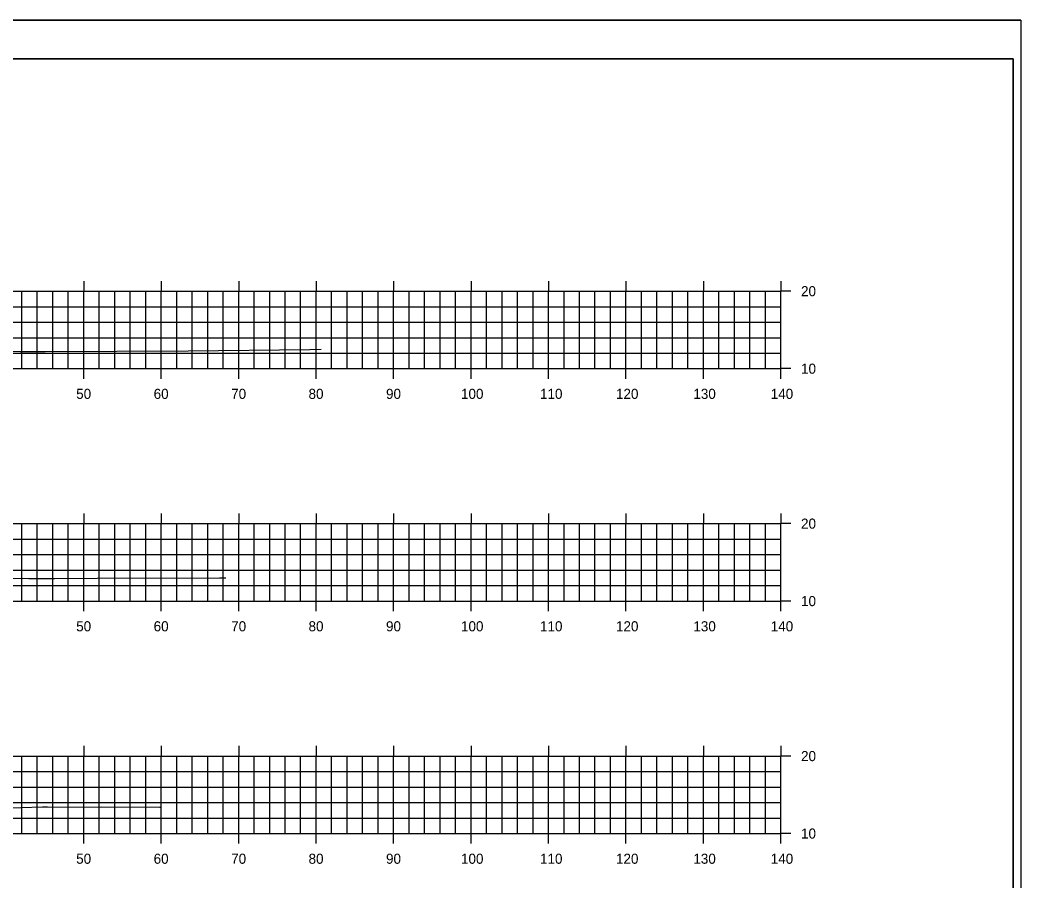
# Model space of a CAD drawing. Extents: x 40011 to 50684, y 49949 to 72236.
# Drawn here: x 42283.1 to 42412.4, y 69083.5 to 69194.6 of the extents above; entities that cross this region are included whole.
import ezdxf

# ---------------------------------------------------------------- set-up
doc = ezdxf.new("R2010")
doc.units = 0
for name, color, linetype in [('1', 7, 'Continuous'), ('41', 7, 'Continuous'), ('51', 7, 'Continuous'), ('53', 7, 'Continuous'), ('55', 7, 'Continuous'), ('57', 7, 'Continuous'), ('60', 7, 'Continuous')]:
    doc.layers.add(name, color=color, linetype=linetype)

msp = doc.modelspace()

# ---------------------------------------------------------------- linework, layer by layer
at = {"layer": '1'}
for p, q in [((42412.37, 69194.6), (42062.98, 69194.6)), ((42411.37, 69189.6), (42081.37, 69189.6)), ((42411.37, 68979.6), (42411.37, 69189.6))]:
    msp.add_line(p, q, dxfattribs=at)
at = {"layer": '41'}
for points in [[(42062.98, 69194.6), (42412.37, 69194.6), (42412.37, 68974.6), (42062.98, 68974.6)], [(42081.37, 69189.6), (42411.37, 69189.6), (42411.37, 68979.6), (42081.37, 68979.6)]]:
    msp.add_lwpolyline(points, close=True, dxfattribs=at)
at = {"layer": '51'}
for p, q in [((42283.37, 69149.6), (42283.37, 69159.6)), ((42285.37, 69149.6), (42285.37, 69159.6)), ((42287.37, 69149.6), (42287.37, 69159.6)), ((42289.37, 69149.6), (42289.37, 69159.6)), ((42293.37, 69149.6), (42293.37, 69159.6)), ((42295.37, 69149.6), (42295.37, 69159.6)), ((42297.37, 69149.6), (42297.37, 69159.6)), ((42299.37, 69149.6), (42299.37, 69159.6)), ((42303.37, 69149.6), (42303.37, 69159.6)), ((42305.37, 69149.6), (42305.37, 69159.6)), ((42307.37, 69149.6), (42307.37, 69159.6)), ((42309.37, 69149.6), (42309.37, 69159.6)), ((42313.37, 69149.6), (42313.37, 69159.6)), ((42315.37, 69149.6), (42315.37, 69159.6)), ((42317.37, 69149.6), (42317.37, 69159.6)), ((42319.37, 69149.6), (42319.37, 69159.6)), ((42323.37, 69149.6), (42323.37, 69159.6)), ((42325.37, 69149.6), (42325.37, 69159.6)), ((42327.37, 69149.6), (42327.37, 69159.6)), ((42329.37, 69149.6), (42329.37, 69159.6)), ((42333.37, 69149.6), (42333.37, 69159.6)), ((42335.37, 69149.6), (42335.37, 69159.6)), ((42337.37, 69149.6), (42337.37, 69159.6)), ((42339.37, 69149.6), (42339.37, 69159.6)), ((42343.37, 69149.6), (42343.37, 69159.6)), ((42345.37, 69149.6), (42345.37, 69159.6)), ((42347.37, 69149.6), (42347.37, 69159.6)), ((42349.37, 69149.6), (42349.37, 69159.6)), ((42353.37, 69149.6), (42353.37, 69159.6)), ((42355.37, 69149.6), (42355.37, 69159.6)), ((42357.37, 69149.6), (42357.37, 69159.6)), ((42359.37, 69149.6), (42359.37, 69159.6)), ((42363.37, 69149.6), (42363.37, 69159.6)), ((42365.37, 69149.6), (42365.37, 69159.6)), ((42367.37, 69149.6), (42367.37, 69159.6)), ((42369.37, 69149.6), (42369.37, 69159.6)), ((42373.37, 69149.6), (42373.37, 69159.6)), ((42375.37, 69149.6), (42375.37, 69159.6)), ((42377.37, 69149.6), (42377.37, 69159.6)), ((42379.37, 69149.6), (42379.37, 69159.6)), ((42381.37, 69149.6), (42381.37, 69159.6)), ((42382.67, 69159.6), (42381.37, 69159.6)), ((42101.37, 69149.6), (42381.37, 69149.6)), ((42291.37, 69148.3), (42291.37, 69149.6)), ((42301.37, 69148.3), (42301.37, 69149.6)), ((42311.37, 69148.3), (42311.37, 69149.6)), ((42321.37, 69148.3), (42321.37, 69149.6)), ((42331.37, 69148.3), (42331.37, 69149.6)), ((42341.37, 69148.3), (42341.37, 69149.6)), ((42351.37, 69148.3), (42351.37, 69149.6)), ((42361.37, 69148.3), (42361.37, 69149.6)), ((42371.37, 69148.3), (42371.37, 69149.6)), ((42381.37, 69148.3), (42381.37, 69149.6)), ((42382.67, 69149.6), (42381.37, 69149.6)), ((42283.37, 69119.6), (42283.37, 69129.6)), ((42285.37, 69119.6), (42285.37, 69129.6)), ((42287.37, 69119.6), (42287.37, 69129.6)), ((42289.37, 69119.6), (42289.37, 69129.6)), ((42293.37, 69119.6), (42293.37, 69129.6)), ((42295.37, 69119.6), (42295.37, 69129.6)), ((42297.37, 69119.6), (42297.37, 69129.6)), ((42299.37, 69119.6), (42299.37, 69129.6)), ((42303.37, 69119.6), (42303.37, 69129.6)), ((42305.37, 69119.6), (42305.37, 69129.6)), ((42307.37, 69119.6), (42307.37, 69129.6)), ((42309.37, 69119.6), (42309.37, 69129.6)), ((42313.37, 69119.6), (42313.37, 69129.6)), ((42315.37, 69119.6), (42315.37, 69129.6)), ((42317.37, 69119.6), (42317.37, 69129.6)), ((42319.37, 69119.6), (42319.37, 69129.6)), ((42323.37, 69119.6), (42323.37, 69129.6)), ((42325.37, 69119.6), (42325.37, 69129.6)), ((42327.37, 69119.6), (42327.37, 69129.6)), ((42329.37, 69119.6), (42329.37, 69129.6)), ((42333.37, 69119.6), (42333.37, 69129.6)), ((42335.37, 69119.6), (42335.37, 69129.6)), ((42337.37, 69119.6), (42337.37, 69129.6)), ((42339.37, 69119.6), (42339.37, 69129.6)), ((42343.37, 69119.6), (42343.37, 69129.6)), ((42345.37, 69119.6), (42345.37, 69129.6)), ((42347.37, 69119.6), (42347.37, 69129.6)), ((42349.37, 69119.6), (42349.37, 69129.6)), ((42353.37, 69119.6), (42353.37, 69129.6)), ((42355.37, 69119.6), (42355.37, 69129.6)), ((42357.37, 69119.6), (42357.37, 69129.6)), ((42359.37, 69119.6), (42359.37, 69129.6)), ((42363.37, 69119.6), (42363.37, 69129.6)), ((42365.37, 69119.6), (42365.37, 69129.6)), ((42367.37, 69119.6), (42367.37, 69129.6)), ((42369.37, 69119.6), (42369.37, 69129.6)), ((42373.37, 69119.6), (42373.37, 69129.6)), ((42375.37, 69119.6), (42375.37, 69129.6)), ((42377.37, 69119.6), (42377.37, 69129.6)), ((42379.37, 69119.6), (42379.37, 69129.6)), ((42381.37, 69119.6), (42381.37, 69129.6)), ((42382.67, 69129.6), (42381.37, 69129.6)), ((42101.37, 69119.6), (42381.37, 69119.6)), ((42291.37, 69118.3), (42291.37, 69119.6)), ((42301.37, 69118.3), (42301.37, 69119.6)), ((42311.37, 69118.3), (42311.37, 69119.6)), ((42321.37, 69118.3), (42321.37, 69119.6)), ((42331.37, 69118.3), (42331.37, 69119.6)), ((42341.37, 69118.3), (42341.37, 69119.6)), ((42351.37, 69118.3), (42351.37, 69119.6)), ((42361.37, 69118.3), (42361.37, 69119.6)), ((42371.37, 69118.3), (42371.37, 69119.6)), ((42381.37, 69118.3), (42381.37, 69119.6)), ((42382.67, 69119.6), (42381.37, 69119.6)), ((42283.37, 69089.6), (42283.37, 69099.6)), ((42285.37, 69089.6), (42285.37, 69099.6)), ((42287.37, 69089.6), (42287.37, 69099.6)), ((42289.37, 69089.6), (42289.37, 69099.6)), ((42293.37, 69089.6), (42293.37, 69099.6)), ((42295.37, 69089.6), (42295.37, 69099.6)), ((42297.37, 69089.6), (42297.37, 69099.6)), ((42299.37, 69089.6), (42299.37, 69099.6)), ((42303.37, 69089.6), (42303.37, 69099.6)), ((42305.37, 69089.6), (42305.37, 69099.6)), ((42307.37, 69089.6), (42307.37, 69099.6)), ((42309.37, 69089.6), (42309.37, 69099.6)), ((42313.37, 69089.6), (42313.37, 69099.6)), ((42315.37, 69089.6), (42315.37, 69099.6)), ((42317.37, 69089.6), (42317.37, 69099.6)), ((42319.37, 69089.6), (42319.37, 69099.6)), ((42323.37, 69089.6), (42323.37, 69099.6)), ((42325.37, 69089.6), (42325.37, 69099.6)), ((42327.37, 69089.6), (42327.37, 69099.6)), ((42329.37, 69089.6), (42329.37, 69099.6)), ((42333.37, 69089.6), (42333.37, 69099.6)), ((42335.37, 69089.6), (42335.37, 69099.6)), ((42337.37, 69089.6), (42337.37, 69099.6)), ((42339.37, 69089.6), (42339.37, 69099.6)), ((42343.37, 69089.6), (42343.37, 69099.6)), ((42345.37, 69089.6), (42345.37, 69099.6)), ((42347.37, 69089.6), (42347.37, 69099.6)), ((42349.37, 69089.6), (42349.37, 69099.6)), ((42353.37, 69089.6), (42353.37, 69099.6)), ((42355.37, 69089.6), (42355.37, 69099.6)), ((42357.37, 69089.6), (42357.37, 69099.6)), ((42359.37, 69089.6), (42359.37, 69099.6)), ((42363.37, 69089.6), (42363.37, 69099.6)), ((42365.37, 69089.6), (42365.37, 69099.6)), ((42367.37, 69089.6), (42367.37, 69099.6)), ((42369.37, 69089.6), (42369.37, 69099.6)), ((42373.37, 69089.6), (42373.37, 69099.6)), ((42375.37, 69089.6), (42375.37, 69099.6)), ((42377.37, 69089.6), (42377.37, 69099.6)), ((42379.37, 69089.6), (42379.37, 69099.6)), ((42381.37, 69089.6), (42381.37, 69099.6)), ((42382.67, 69099.6), (42381.37, 69099.6)), ((42101.37, 69089.6), (42381.37, 69089.6)), ((42291.37, 69088.3), (42291.37, 69089.6)), ((42301.37, 69088.3), (42301.37, 69089.6)), ((42311.37, 69088.3), (42311.37, 69089.6)), ((42321.37, 69088.3), (42321.37, 69089.6)), ((42331.37, 69088.3), (42331.37, 69089.6)), ((42341.37, 69088.3), (42341.37, 69089.6)), ((42351.37, 69088.3), (42351.37, 69089.6)), ((42361.37, 69088.3), (42361.37, 69089.6)), ((42371.37, 69088.3), (42371.37, 69089.6)), ((42381.37, 69088.3), (42381.37, 69089.6)), ((42382.67, 69089.6), (42381.37, 69089.6))]:
    msp.add_line(p, q, dxfattribs=at)
at = {"layer": '53'}
for p, q in [((42101.37, 69157.6), (42381.37, 69157.6)), ((42101.37, 69155.6), (42381.37, 69155.6)), ((42101.37, 69153.6), (42381.37, 69153.6)), ((42101.37, 69151.6), (42381.37, 69151.6)), ((42101.37, 69127.6), (42381.37, 69127.6)), ((42101.37, 69125.6), (42381.37, 69125.6)), ((42101.37, 69123.6), (42381.37, 69123.6)), ((42101.37, 69121.6), (42381.37, 69121.6)), ((42101.37, 69097.6), (42381.37, 69097.6)), ((42101.37, 69095.6), (42381.37, 69095.6)), ((42101.37, 69093.6), (42381.37, 69093.6)), ((42101.37, 69091.6), (42381.37, 69091.6))]:
    msp.add_line(p, q, dxfattribs=at)
at = {"layer": '55'}
for p, q in [((42101.37, 69159.6), (42381.37, 69159.6)), ((42291.37, 69149.6), (42291.37, 69159.6)), ((42301.37, 69149.6), (42301.37, 69159.6)), ((42311.37, 69149.6), (42311.37, 69159.6)), ((42321.37, 69149.6), (42321.37, 69159.6)), ((42331.37, 69149.6), (42331.37, 69159.6)), ((42341.37, 69149.6), (42341.37, 69159.6)), ((42351.37, 69149.6), (42351.37, 69159.6)), ((42361.37, 69149.6), (42361.37, 69159.6)), ((42371.37, 69149.6), (42371.37, 69159.6)), ((42381.37, 69149.6), (42381.37, 69159.6)), ((42101.37, 69149.6), (42381.37, 69149.6)), ((42101.37, 69129.6), (42381.37, 69129.6)), ((42291.37, 69119.6), (42291.37, 69129.6)), ((42301.37, 69119.6), (42301.37, 69129.6)), ((42311.37, 69119.6), (42311.37, 69129.6)), ((42321.37, 69119.6), (42321.37, 69129.6)), ((42331.37, 69119.6), (42331.37, 69129.6)), ((42341.37, 69119.6), (42341.37, 69129.6)), ((42351.37, 69119.6), (42351.37, 69129.6)), ((42361.37, 69119.6), (42361.37, 69129.6)), ((42371.37, 69119.6), (42371.37, 69129.6)), ((42381.37, 69119.6), (42381.37, 69129.6)), ((42101.37, 69119.6), (42381.37, 69119.6)), ((42101.37, 69099.6), (42381.37, 69099.6)), ((42291.37, 69089.6), (42291.37, 69099.6)), ((42301.37, 69089.6), (42301.37, 69099.6)), ((42311.37, 69089.6), (42311.37, 69099.6)), ((42321.37, 69089.6), (42321.37, 69099.6)), ((42331.37, 69089.6), (42331.37, 69099.6)), ((42341.37, 69089.6), (42341.37, 69099.6)), ((42351.37, 69089.6), (42351.37, 69099.6)), ((42361.37, 69089.6), (42361.37, 69099.6)), ((42371.37, 69089.6), (42371.37, 69099.6)), ((42381.37, 69089.6), (42381.37, 69099.6)), ((42101.37, 69089.6), (42381.37, 69089.6))]:
    msp.add_line(p, q, dxfattribs=at)
at = {"layer": '57'}
for points in [[(42271.7, 69151.84), (42283.17, 69151.8), (42286.39, 69151.83), (42304.85, 69151.9), (42320.54, 69152.09), (42322.02, 69152.1)], [(42276.99, 69122.64), (42284.27, 69122.52), (42284.29, 69122.53), (42284.52, 69122.52), (42287.58, 69122.53), (42293.11, 69122.54), (42308.9, 69122.6), (42309.27, 69122.6), (42309.69, 69122.61)], [(42280.39, 69092.86), (42286.06, 69093.03), (42286.7, 69093.03), (42293.41, 69093.01), (42293.7, 69093.03), (42301.17, 69093), (42301.24, 69092.99), (42301.33, 69092.99)]]:
    msp.add_lwpolyline(points, dxfattribs=at)
at = {"layer": '60'}
for p, q in [((42291.37, 69160.9), (42291.37, 69159.6)), ((42301.37, 69160.9), (42301.37, 69159.6)), ((42311.37, 69160.9), (42311.37, 69159.6)), ((42321.37, 69160.9), (42321.37, 69159.6)), ((42331.37, 69160.9), (42331.37, 69159.6)), ((42341.37, 69160.9), (42341.37, 69159.6)), ((42351.37, 69160.9), (42351.37, 69159.6)), ((42361.37, 69160.9), (42361.37, 69159.6)), ((42371.37, 69160.9), (42371.37, 69159.6)), ((42381.37, 69160.9), (42381.37, 69159.6)), ((42291.37, 69130.9), (42291.37, 69129.6)), ((42301.37, 69130.9), (42301.37, 69129.6)), ((42311.37, 69130.9), (42311.37, 69129.6)), ((42321.37, 69130.9), (42321.37, 69129.6)), ((42331.37, 69130.9), (42331.37, 69129.6)), ((42341.37, 69130.9), (42341.37, 69129.6)), ((42351.37, 69130.9), (42351.37, 69129.6)), ((42361.37, 69130.9), (42361.37, 69129.6)), ((42371.37, 69130.9), (42371.37, 69129.6)), ((42381.37, 69130.9), (42381.37, 69129.6)), ((42291.37, 69100.9), (42291.37, 69099.6)), ((42301.37, 69100.9), (42301.37, 69099.6)), ((42311.37, 69100.9), (42311.37, 69099.6)), ((42321.37, 69100.9), (42321.37, 69099.6)), ((42331.37, 69100.9), (42331.37, 69099.6)), ((42341.37, 69100.9), (42341.37, 69099.6)), ((42351.37, 69100.9), (42351.37, 69099.6)), ((42361.37, 69100.9), (42361.37, 69099.6)), ((42371.37, 69100.9), (42371.37, 69099.6)), ((42381.37, 69100.9), (42381.37, 69099.6))]:
    msp.add_line(p, q, dxfattribs=at)

# ---------------------------------------------------------------- texts
at = {"layer": '51'}
for s, p in [('20', (42383.97, 69158.95)), ('10', (42383.97, 69148.95)), ('50', (42290.39, 69145.7)), ('60', (42300.39, 69145.7)), ('70', (42310.4, 69145.7)), ('80', (42320.39, 69145.7)), ('90', (42330.39, 69145.7)), ('100', (42340.07, 69145.7)), ('110', (42350.27, 69145.7)), ('120', (42360.08, 69145.7)), ('130', (42370.07, 69145.7)), ('140', (42380.06, 69145.7)), ('20', (42383.97, 69128.95)), ('10', (42383.97, 69118.95)), ('50', (42290.39, 69115.7)), ('60', (42300.39, 69115.7)), ('70', (42310.4, 69115.7)), ('80', (42320.39, 69115.7)), ('90', (42330.39, 69115.7)), ('100', (42340.07, 69115.7)), ('110', (42350.27, 69115.7)), ('120', (42360.08, 69115.7)), ('130', (42370.07, 69115.7)), ('140', (42380.06, 69115.7)), ('20', (42383.97, 69098.95)), ('10', (42383.97, 69088.95)), ('50', (42290.39, 69085.7)), ('60', (42300.39, 69085.7)), ('70', (42310.4, 69085.7)), ('80', (42320.39, 69085.7)), ('90', (42330.39, 69085.7)), ('100', (42340.07, 69085.7)), ('110', (42350.27, 69085.7)), ('120', (42360.08, 69085.7)), ('130', (42370.07, 69085.7)), ('140', (42380.06, 69085.7))]:
    msp.add_text(s, height=1.3, dxfattribs=at).set_placement(p)

doc.saveas('drawing.dxf')
